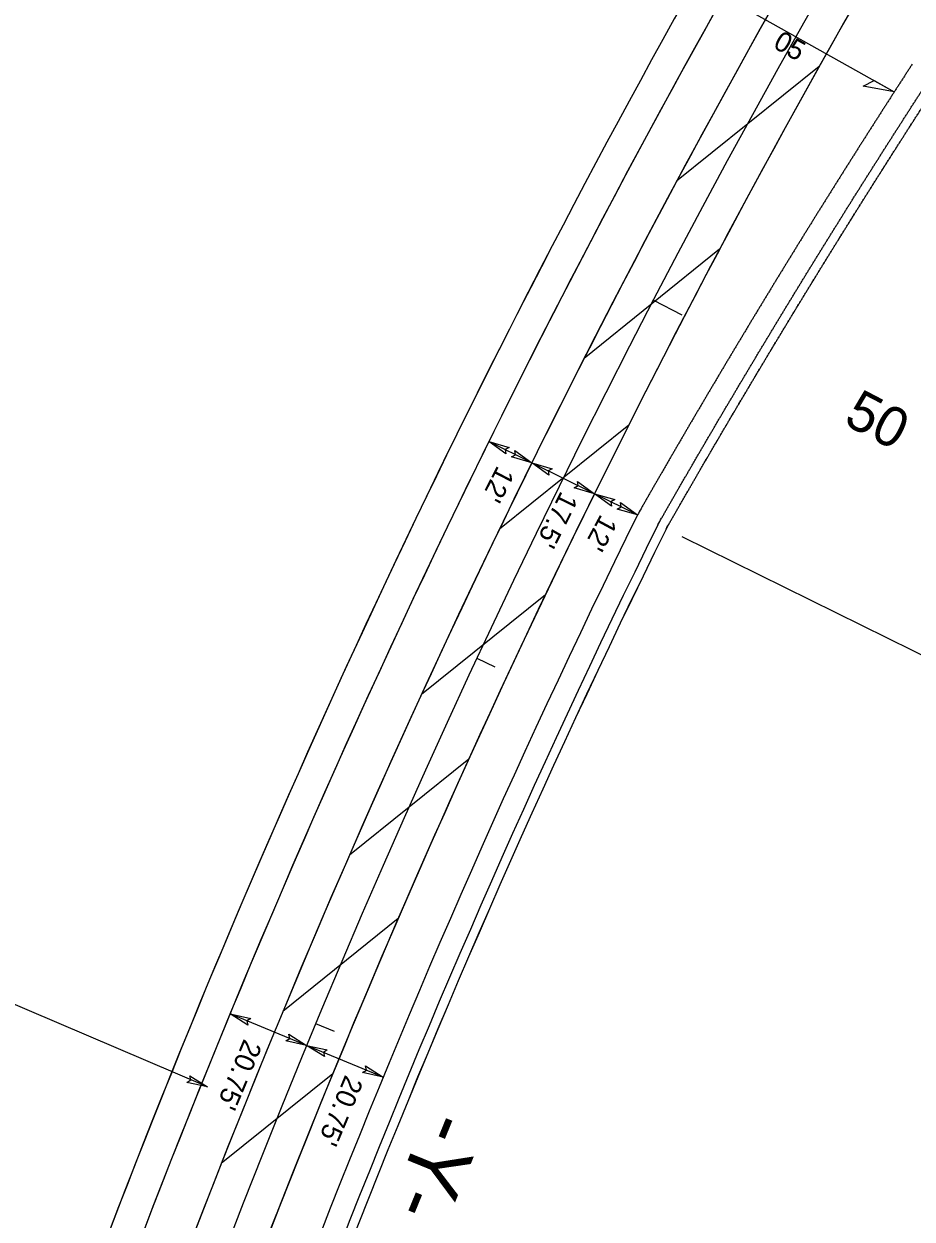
# Model space of a CAD drawing. Extents: x 1778969 to 1790720, y 807089 to 817794.
# Drawn here: x 1781084.1 to 1781306.5, y 812371.1 to 812670.4 of the extents above; entities that cross this region are included whole.
import ezdxf

# ---------------------------------------------------------------- set-up
doc = ezdxf.new("R2010")
doc.units = 0
for name, color, linetype in [('Prop CMT Guardrail Graphics', 7, 'Continuous'), ('Prop Conc Shoulder Berm Gutter', 7, 'Continuous'), ('Prop Dimension', 7, 'Continuous'), ('Prop Dimension Text', 7, 'Continuous'), ('Prop DSN Text', 7, 'Continuous'), ('Prop EOT', 7, 'Continuous'), ('Prop Guardrail', 7, 'Continuous'), ('Prop Hatching', 7, 'Continuous'), ('Prop Horizontal Alignment', 7, 'Continuous'), ('Prop Horizontal Alignment Station Label', 7, 'Continuous'), ('Prop Horizontal Alignment Tick Label', 7, 'Continuous'), ('Prop Horizontal Alignment Tick Large', 7, 'Continuous'), ('Prop Horizontal Alignment Tick Small', 7, 'Continuous'), ('Prop Lane Lines', 7, 'Continuous'), ('Prop Paved Shoulder', 7, 'Continuous'), ('Prop Superelevation  Arrow CELL', 7, 'Continuous'), ('Prop Superelevation Label', 7, 'Continuous'), ('Prop Terminator CELL', 7, 'Continuous'), ('Scratch_Level_3', 7, 'Continuous'), ('Scratch_Level_7', 7, 'Continuous')]:
    doc.layers.add(name, color=color, linetype=linetype)

msp = doc.modelspace()

# ---------------------------------------------------------------- linework, layer by layer
at = {"layer": 'Prop CMT Guardrail Graphics'}
msp.add_arc((1783308.81, 811525.98), 2358.75, 152.51849, 162.35467, dxfattribs=at)
at = {"layer": 'Prop Conc Shoulder Berm Gutter'}
msp.add_arc((1783308.81, 811525.98), 2303.58, 153.74801, 164.19896, dxfattribs=at)
for points in [[(1781276.42, 812601.84), (1781276.89, 812602.6), (1781277.35, 812603.36), (1781277.82, 812604.12), (1781278.28, 812604.88), (1781278.75, 812605.64), (1781279.21, 812606.4), (1781279.68, 812607.16), (1781280.14, 812607.92), (1781280.61, 812608.67), (1781281.08, 812609.43), (1781281.54, 812610.19), (1781282.01, 812610.95), (1781282.48, 812611.71), (1781282.94, 812612.47), (1781283.41, 812613.22), (1781283.88, 812613.98), (1781284.35, 812614.74), (1781284.82, 812615.5), (1781285.29, 812616.25), (1781285.76, 812617.01), (1781286.23, 812617.77), (1781286.7, 812618.52), (1781287.17, 812619.28), (1781287.64, 812620.03), (1781288.11, 812620.79), (1781288.58, 812621.54), (1781289.05, 812622.3), (1781289.52, 812623.06), (1781289.99, 812623.81), (1781290.46, 812624.56), (1781290.94, 812625.32), (1781291.41, 812626.07), (1781291.88, 812626.83), (1781292.36, 812627.58), (1781292.83, 812628.34), (1781293.3, 812629.09), (1781293.78, 812629.84), (1781294.25, 812630.59), (1781294.73, 812631.35), (1781295.2, 812632.1), (1781295.68, 812632.85), (1781296.15, 812633.61), (1781296.63, 812634.36), (1781297.1, 812635.11), (1781297.58, 812635.86), (1781298.06, 812636.61), (1781298.53, 812637.36), (1781299.01, 812638.11), (1781299.49, 812638.87), (1781299.97, 812639.62), (1781300.44, 812640.37), (1781300.92, 812641.12), (1781301.4, 812641.87), (1781301.88, 812642.62), (1781302.36, 812643.37), (1781302.84, 812644.12), (1781303.32, 812644.86), (1781303.8, 812645.61), (1781304.28, 812646.36), (1781304.76, 812647.11), (1781305.24, 812647.86), (1781305.72, 812648.61), (1781306.2, 812649.36), (1781306.68, 812650.1), (1781307.17, 812650.85), (1781307.65, 812651.6), (1781308.13, 812652.35), (1781308.61, 812653.09), (1781309.1, 812653.84), (1781309.58, 812654.59), (1781310.06, 812655.33), (1781310.55, 812656.08), (1781311.03, 812656.82), (1781311.51, 812657.57)], [(1781242.82, 812544.9), (1781243.78, 812546.57), (1781244.22, 812547.35), (1781244.66, 812548.12), (1781245.11, 812548.9), (1781245.55, 812549.67), (1781245.99, 812550.44), (1781246.44, 812551.22), (1781246.88, 812551.99), (1781247.33, 812552.76), (1781247.77, 812553.54), (1781248.22, 812554.31), (1781248.67, 812555.08), (1781249.11, 812555.85), (1781249.56, 812556.63), (1781250.01, 812557.4), (1781250.45, 812558.17), (1781250.9, 812558.94), (1781251.35, 812559.71), (1781251.8, 812560.48), (1781252.25, 812561.25), (1781252.69, 812562.02), (1781253.14, 812562.8), (1781253.59, 812563.57), (1781254.04, 812564.34), (1781254.49, 812565.11), (1781254.94, 812565.88), (1781255.39, 812566.65), (1781255.84, 812567.41), (1781256.3, 812568.18), (1781256.75, 812568.95), (1781257.2, 812569.72), (1781257.65, 812570.49), (1781258.1, 812571.26), (1781258.55, 812572.03), (1781259.01, 812572.8), (1781259.46, 812573.56), (1781259.91, 812574.33), (1781260.37, 812575.1), (1781260.82, 812575.87), (1781261.28, 812576.63), (1781261.73, 812577.4), (1781262.18, 812578.17), (1781262.64, 812578.93), (1781263.1, 812579.7), (1781263.55, 812580.47), (1781264.01, 812581.23), (1781264.46, 812582), (1781264.92, 812582.76), (1781265.38, 812583.53), (1781265.83, 812584.29), (1781266.29, 812585.06), (1781266.75, 812585.82), (1781267.21, 812586.59), (1781267.66, 812587.35), (1781268.12, 812588.12), (1781268.58, 812588.88), (1781269.04, 812589.64), (1781269.5, 812590.41), (1781269.96, 812591.17), (1781270.42, 812591.93), (1781270.88, 812592.7), (1781271.34, 812593.46), (1781271.8, 812594.22), (1781272.26, 812594.99), (1781272.72, 812595.75), (1781273.18, 812596.51), (1781273.65, 812597.27), (1781274.11, 812598.03), (1781274.57, 812598.79), (1781275.03, 812599.56), (1781275.5, 812600.32), (1781275.96, 812601.08), (1781276.42, 812601.84)]]:
    msp.add_spline(points, degree=3, dxfattribs=at)
at = {"layer": 'Prop Dimension'}
for p, q in [((1781211.28, 812560.45), (1781200.52, 812565.76)), ((1781226.98, 812552.71), (1781211.28, 812560.45)), ((1781237.74, 812547.4), (1781226.98, 812552.71)), ((1781314.16, 812509.72), (1781248.9, 812541.9)), ((1781154.9, 812414.56), (1781135.72, 812422.47)), ((1781174.08, 812406.64), (1781154.9, 812414.56))]:
    msp.add_line(p, q, dxfattribs=at)
at = {"layer": 'Prop DSN Text'}
msp.add_line((1781130.09, 812404.16), (1780995.62, 812461.49), dxfattribs=at)
at = {"layer": 'Prop EOT'}
for radius, start, end in [(2350.75, 144.08998, 163.35801), (2309.25, 153.74801, 174.52695)]:
    msp.add_arc((1783308.81, 811525.98), radius, start, end, dxfattribs=at)
for points in [[(1781306.51, 812660.24), (1781306.03, 812659.49), (1781305.54, 812658.75), (1781305.06, 812658), (1781304.57, 812657.25), (1781304.09, 812656.5), (1781303.6, 812655.75), (1781303.12, 812655), (1781302.64, 812654.25), (1781302.15, 812653.5), (1781301.67, 812652.76), (1781301.19, 812652.01), (1781300.7, 812651.26), (1781300.22, 812650.51), (1781299.74, 812649.76), (1781299.26, 812649), (1781298.78, 812648.25), (1781298.3, 812647.5), (1781297.82, 812646.75), (1781297.34, 812646), (1781296.85, 812645.25), (1781296.37, 812644.5), (1781295.9, 812643.75), (1781295.42, 812642.99), (1781294.94, 812642.24), (1781294.46, 812641.49), (1781293.98, 812640.74), (1781293.5, 812639.98), (1781293.02, 812639.23), (1781292.55, 812638.48), (1781292.07, 812637.72), (1781291.59, 812636.97), (1781291.12, 812636.21), (1781290.64, 812635.46), (1781290.16, 812634.71), (1781289.69, 812633.95), (1781289.21, 812633.2), (1781288.74, 812632.44), (1781288.26, 812631.69), (1781287.79, 812630.93), (1781287.31, 812630.18), (1781286.84, 812629.42), (1781286.36, 812628.66), (1781285.89, 812627.91), (1781285.42, 812627.15), (1781284.94, 812626.39), (1781284.47, 812625.64), (1781284, 812624.88), (1781283.52, 812624.12), (1781283.05, 812623.37), (1781282.58, 812622.61), (1781282.11, 812621.85), (1781281.64, 812621.09), (1781281.17, 812620.33), (1781280.7, 812619.58), (1781280.23, 812618.82), (1781279.76, 812618.06), (1781279.29, 812617.3), (1781278.82, 812616.54), (1781278.35, 812615.78), (1781277.88, 812615.02), (1781277.41, 812614.26), (1781276.94, 812613.5), (1781276.48, 812612.74), (1781276.01, 812611.98), (1781275.54, 812611.22), (1781275.07, 812610.46), (1781274.61, 812609.7), (1781274.14, 812608.94), (1781273.67, 812608.18), (1781273.21, 812607.41), (1781272.74, 812606.65), (1781272.28, 812605.89), (1781271.81, 812605.13), (1781271.35, 812604.37)], [(1781271.35, 812604.37), (1781270.88, 812603.6), (1781270.42, 812602.84), (1781269.95, 812602.08), (1781269.49, 812601.31), (1781269.03, 812600.55), (1781268.56, 812599.79), (1781268.1, 812599.02), (1781267.64, 812598.26), (1781267.17, 812597.49), (1781266.71, 812596.73), (1781266.25, 812595.97), (1781265.79, 812595.2), (1781265.33, 812594.44), (1781264.87, 812593.67), (1781264.41, 812592.91), (1781263.95, 812592.14), (1781263.49, 812591.37), (1781263.03, 812590.61), (1781262.57, 812589.84), (1781262.11, 812589.08), (1781261.65, 812588.31), (1781261.19, 812587.54), (1781260.73, 812586.78), (1781260.27, 812586.01), (1781259.82, 812585.24), (1781259.36, 812584.47), (1781258.9, 812583.71), (1781258.45, 812582.94), (1781257.99, 812582.17), (1781257.53, 812581.4), (1781257.08, 812580.63), (1781256.62, 812579.86), (1781256.17, 812579.1), (1781255.71, 812578.33), (1781255.26, 812577.56), (1781254.8, 812576.79), (1781254.35, 812576.02), (1781253.89, 812575.25), (1781253.44, 812574.48), (1781252.99, 812573.71), (1781252.53, 812572.94), (1781252.08, 812572.17), (1781251.63, 812571.4), (1781251.17, 812570.63), (1781250.72, 812569.85), (1781250.27, 812569.08), (1781249.82, 812568.31), (1781249.37, 812567.54), (1781248.92, 812566.77), (1781248.47, 812565.99), (1781248.02, 812565.22), (1781247.57, 812564.45), (1781247.12, 812563.68), (1781246.67, 812562.9), (1781246.22, 812562.13), (1781245.77, 812561.36), (1781245.32, 812560.58), (1781244.87, 812559.81), (1781244.43, 812559.04), (1781243.98, 812558.26), (1781243.53, 812557.49), (1781243.08, 812556.71), (1781242.64, 812555.94), (1781242.19, 812555.16), (1781241.74, 812554.39), (1781241.3, 812553.61), (1781240.85, 812552.84), (1781240.41, 812552.06), (1781239.96, 812551.29), (1781239.52, 812550.51), (1781239.07, 812549.73), (1781238.63, 812548.96), (1781237.74, 812547.4)]]:
    msp.add_spline(points, degree=3, dxfattribs=at)
at = {"layer": 'Prop Guardrail'}
for radius, start, end in [(2358.75, 144.08998, 162.35467), (2301.25, 153.74801, 164.19128)]:
    msp.add_arc((1783308.81, 811525.98), radius, start, end, dxfattribs=at)
for points in [[(1781278.42, 812600.62), (1781278.88, 812601.38), (1781279.34, 812602.14), (1781279.81, 812602.9), (1781280.27, 812603.66), (1781280.74, 812604.42), (1781281.2, 812605.18), (1781281.67, 812605.94), (1781282.13, 812606.69), (1781282.6, 812607.45), (1781283.06, 812608.21), (1781283.53, 812608.97), (1781284, 812609.73), (1781284.46, 812610.48), (1781284.93, 812611.24), (1781285.4, 812612), (1781285.87, 812612.75), (1781286.33, 812613.51), (1781286.8, 812614.27), (1781287.27, 812615.02), (1781287.74, 812615.78), (1781288.21, 812616.53), (1781288.68, 812617.29), (1781289.15, 812618.05), (1781289.62, 812618.8), (1781290.09, 812619.56), (1781290.56, 812620.31), (1781291.03, 812621.06), (1781291.5, 812621.82), (1781291.97, 812622.57), (1781292.44, 812623.33), (1781292.91, 812624.08), (1781293.39, 812624.83), (1781293.86, 812625.59), (1781294.33, 812626.34), (1781294.8, 812627.09), (1781295.28, 812627.85), (1781295.75, 812628.6), (1781296.23, 812629.35), (1781296.7, 812630.1), (1781297.17, 812630.85), (1781297.65, 812631.61), (1781298.12, 812632.36), (1781298.6, 812633.11), (1781299.07, 812633.86), (1781299.55, 812634.61), (1781300.03, 812635.36), (1781300.5, 812636.11), (1781300.98, 812636.86), (1781301.46, 812637.61), (1781301.93, 812638.36), (1781302.41, 812639.11), (1781302.89, 812639.86), (1781303.37, 812640.61), (1781303.85, 812641.36), (1781304.32, 812642.11), (1781304.8, 812642.86), (1781305.28, 812643.61), (1781305.76, 812644.35), (1781306.24, 812645.1), (1781306.72, 812645.85), (1781307.2, 812646.6), (1781307.68, 812647.34), (1781308.16, 812648.09), (1781308.64, 812648.84), (1781309.13, 812649.59), (1781309.61, 812650.33), (1781310.09, 812651.08), (1781310.57, 812651.83), (1781311.05, 812652.57), (1781311.54, 812653.32), (1781312.02, 812654.06), (1781312.5, 812654.81), (1781312.99, 812655.55), (1781313.47, 812656.3)], [(1781244.92, 812543.87), (1781245.8, 812545.41), (1781246.24, 812546.19), (1781246.69, 812546.96), (1781247.13, 812547.73), (1781247.57, 812548.51), (1781248.02, 812549.28), (1781248.46, 812550.05), (1781248.91, 812550.83), (1781249.35, 812551.6), (1781249.8, 812552.37), (1781250.24, 812553.14), (1781250.69, 812553.91), (1781251.13, 812554.69), (1781251.58, 812555.46), (1781252.03, 812556.23), (1781252.47, 812557), (1781252.92, 812557.77), (1781253.37, 812558.54), (1781253.81, 812559.31), (1781254.26, 812560.08), (1781254.71, 812560.85), (1781255.16, 812561.62), (1781255.61, 812562.39), (1781256.06, 812563.16), (1781256.51, 812563.93), (1781256.96, 812564.7), (1781257.41, 812565.47), (1781257.86, 812566.24), (1781258.31, 812567), (1781258.76, 812567.77), (1781259.21, 812568.54), (1781259.66, 812569.31), (1781260.11, 812570.08), (1781260.56, 812570.84), (1781261.02, 812571.61), (1781261.47, 812572.38), (1781261.92, 812573.14), (1781262.38, 812573.91), (1781262.83, 812574.68), (1781263.28, 812575.44), (1781263.74, 812576.21), (1781264.19, 812576.98), (1781264.65, 812577.74), (1781265.1, 812578.51), (1781265.56, 812579.27), (1781266.01, 812580.04), (1781266.47, 812580.8), (1781266.92, 812581.57), (1781267.38, 812582.33), (1781267.84, 812583.1), (1781268.29, 812583.86), (1781268.75, 812584.62), (1781269.21, 812585.39), (1781269.67, 812586.15), (1781270.12, 812586.92), (1781270.58, 812587.68), (1781271.04, 812588.44), (1781271.5, 812589.2), (1781271.96, 812589.97), (1781272.42, 812590.73), (1781272.88, 812591.49), (1781273.34, 812592.25), (1781273.8, 812593.02), (1781274.26, 812593.78), (1781274.72, 812594.54), (1781275.18, 812595.3), (1781275.64, 812596.06), (1781276.1, 812596.82), (1781276.57, 812597.58), (1781277.03, 812598.34), (1781277.49, 812599.1), (1781277.95, 812599.86), (1781278.42, 812600.62)]]:
    msp.add_spline(points, degree=3, dxfattribs=at)
at = {"layer": 'Prop Hatching'}
for p, q in [((1781283.27, 812659.73), (1781247.55, 812630.95)), ((1781258.31, 812613.93), (1781224.38, 812586.6)), ((1781235.55, 812569.91), (1781203.16, 812543.81)), ((1781214.7, 812527.42), (1781183.64, 812502.4)), ((1781195.51, 812486.28), (1781165.63, 812462.2)), ((1781177.81, 812446.34), (1781148.96, 812423.09)), ((1781161.44, 812407.46), (1781133.52, 812384.96))]:
    msp.add_line(p, q, dxfattribs=at)
at = {"layer": 'Prop Horizontal Alignment'}
msp.add_arc((1783308.81, 811525.98), 2330, 144.08998, 185.35942, dxfattribs=at)
at = {"layer": 'Prop Horizontal Alignment Tick Large'}
msp.add_line((1781241.73, 812601.19), (1781248.82, 812597.49), dxfattribs=at)
at = {"layer": 'Prop Horizontal Alignment Tick Small'}
for p, q in [((1781197.5, 812511.51), (1781202.03, 812509.39)), ((1781157.16, 812420.01), (1781161.78, 812418.09))]:
    msp.add_line(p, q, dxfattribs=at)
at = {"layer": 'Prop Lane Lines'}
for radius, start in [(2338.75, 144.36073), (2321.25, 144.3813), (2338.75, 148.12573), (2321.25, 148.12573), (2321.25, 153.74801)]:
    msp.add_arc((1783308.81, 811525.98), radius, start, 163.33829, dxfattribs=at)
at = {"layer": 'Prop Paved Shoulder'}
msp.add_arc((1783308.81, 811525.98), 2358.75, 144.08998, 162.35467, dxfattribs=at)
at = {"layer": 'Prop Superelevation  Arrow CELL'}
msp.add_line((1781259.31, 812677.32), (1781302.03, 812653.32), dxfattribs=at)
msp.add_lwpolyline([(1781302.03, 812653.32), (1781294.27, 812654.81), (1781296.99, 812656.15)], close=True, dxfattribs=at)
at = {"layer": 'Prop Terminator CELL'}
for points in [[(1781204.78, 812562.67), (1781200.52, 812565.76), (1781205.6, 812564.28), (1781204.6, 812563.75)], [(1781207.03, 812563.55), (1781211.28, 812560.45), (1781206.2, 812561.93), (1781207.2, 812562.47)], [(1781215.54, 812557.36), (1781211.28, 812560.45), (1781216.37, 812558.97), (1781215.37, 812558.44)], [(1781222.72, 812555.81), (1781226.98, 812552.71), (1781221.9, 812554.19), (1781222.9, 812554.73)], [(1781231.23, 812549.62), (1781226.98, 812552.71), (1781232.06, 812551.23), (1781231.06, 812550.7)], [(1781233.49, 812550.5), (1781237.74, 812547.4), (1781232.66, 812548.88), (1781233.66, 812549.42)], [(1781140.17, 812419.67), (1781135.72, 812422.47), (1781140.89, 812421.33), (1781139.92, 812420.73)], [(1781150.45, 812417.36), (1781154.9, 812414.56), (1781149.73, 812415.69), (1781150.69, 812416.29)], [(1781159.35, 812411.75), (1781154.9, 812414.56), (1781160.07, 812413.42), (1781159.11, 812412.82)], [(1781169.63, 812409.44), (1781174.08, 812406.64), (1781168.91, 812407.78), (1781169.87, 812408.38)], [(1781125.64, 812406.96), (1781130.09, 812404.16), (1781124.92, 812405.3), (1781125.88, 812405.9)]]:
    msp.add_lwpolyline(points, close=True, dxfattribs=at)
at = {"layer": 'Scratch_Level_3'}
msp.add_arc((1783308.81, 811525.98), 2350.75, 144.08998, 164.89021, dxfattribs=at)
at = {"layer": 'Scratch_Level_7'}
msp.add_arc((1783308.81, 811525.98), 2301.26, 153.74801, 164.19128, dxfattribs=at)
for points in [[(1781278.41, 812600.63), (1781278.87, 812601.39), (1781279.34, 812602.15), (1781279.8, 812602.91), (1781280.26, 812603.67), (1781280.73, 812604.42), (1781281.19, 812605.18), (1781281.66, 812605.94), (1781282.12, 812606.7), (1781282.59, 812607.46), (1781283.05, 812608.22), (1781283.52, 812608.97), (1781283.99, 812609.73), (1781284.45, 812610.49), (1781284.92, 812611.25), (1781285.39, 812612), (1781285.86, 812612.76), (1781286.32, 812613.52), (1781286.79, 812614.27), (1781287.26, 812615.03), (1781287.73, 812615.78), (1781288.2, 812616.54), (1781288.67, 812617.3), (1781289.14, 812618.05), (1781289.61, 812618.81), (1781290.08, 812619.56), (1781290.55, 812620.32), (1781291.02, 812621.07), (1781291.49, 812621.82), (1781291.96, 812622.58), (1781292.43, 812623.33), (1781292.91, 812624.09), (1781293.38, 812624.84), (1781293.85, 812625.59), (1781294.32, 812626.35), (1781294.8, 812627.1), (1781295.27, 812627.85), (1781295.74, 812628.6), (1781296.22, 812629.36), (1781296.69, 812630.11), (1781297.17, 812630.86), (1781297.64, 812631.61), (1781298.12, 812632.36), (1781298.59, 812633.11), (1781299.07, 812633.87), (1781299.54, 812634.62), (1781300.02, 812635.37), (1781300.49, 812636.12), (1781300.97, 812636.87), (1781301.45, 812637.62), (1781301.93, 812638.37), (1781302.4, 812639.12), (1781302.88, 812639.87), (1781303.36, 812640.62), (1781303.84, 812641.37), (1781304.32, 812642.11), (1781304.8, 812642.86), (1781305.27, 812643.61), (1781305.75, 812644.36), (1781306.23, 812645.11), (1781306.71, 812645.86), (1781307.19, 812646.6), (1781307.67, 812647.35), (1781308.16, 812648.1), (1781308.64, 812648.84), (1781309.12, 812649.59), (1781309.6, 812650.34), (1781310.08, 812651.08), (1781310.56, 812651.83), (1781311.05, 812652.58), (1781311.53, 812653.32), (1781312.01, 812654.07), (1781312.5, 812654.81), (1781312.98, 812655.56), (1781313.46, 812656.3)], [(1781244.91, 812543.87), (1781245.79, 812545.42), (1781246.23, 812546.19), (1781246.68, 812546.97), (1781247.12, 812547.74), (1781247.56, 812548.51), (1781248.01, 812549.29), (1781248.45, 812550.06), (1781248.9, 812550.83), (1781249.34, 812551.6), (1781249.79, 812552.37), (1781250.23, 812553.15), (1781250.68, 812553.92), (1781251.12, 812554.69), (1781251.57, 812555.46), (1781252.02, 812556.23), (1781252.46, 812557), (1781252.91, 812557.77), (1781253.36, 812558.54), (1781253.81, 812559.32), (1781254.25, 812560.09), (1781254.7, 812560.86), (1781255.15, 812561.63), (1781255.6, 812562.39), (1781256.05, 812563.16), (1781256.5, 812563.93), (1781256.95, 812564.7), (1781257.4, 812565.47), (1781257.85, 812566.24), (1781258.3, 812567.01), (1781258.75, 812567.78), (1781259.2, 812568.54), (1781259.65, 812569.31), (1781260.1, 812570.08), (1781260.56, 812570.85), (1781261.01, 812571.62), (1781261.46, 812572.38), (1781261.91, 812573.15), (1781262.37, 812573.92), (1781262.82, 812574.68), (1781263.27, 812575.45), (1781263.73, 812576.22), (1781264.18, 812576.98), (1781264.64, 812577.75), (1781265.09, 812578.51), (1781265.55, 812579.28), (1781266, 812580.04), (1781266.46, 812580.81), (1781266.91, 812581.57), (1781267.37, 812582.34), (1781267.83, 812583.1), (1781268.28, 812583.87), (1781268.74, 812584.63), (1781269.2, 812585.39), (1781269.66, 812586.16), (1781270.11, 812586.92), (1781270.57, 812587.68), (1781271.03, 812588.45), (1781271.49, 812589.21), (1781271.95, 812589.97), (1781272.41, 812590.73), (1781272.87, 812591.5), (1781273.33, 812592.26), (1781273.79, 812593.02), (1781274.25, 812593.78), (1781274.71, 812594.54), (1781275.17, 812595.31), (1781275.63, 812596.07), (1781276.09, 812596.83), (1781276.56, 812597.59), (1781277.02, 812598.35), (1781277.48, 812599.11), (1781277.94, 812599.87), (1781278.41, 812600.63)]]:
    msp.add_spline(points, degree=3, dxfattribs=at)

# ---------------------------------------------------------------- texts
at = {"layer": 'Prop Dimension Text'}
for s, rotation, p in [("12'", 242.9248, (1781202.7, 812559.97)), ("17.5'", 243.5702, (1781218.6, 812553.57)), ("12'", 241.6319, (1781228.56, 812547.79)), ("20.75'", 247.2201, (1781139.24, 812416.39)), ("20.75'", 247.2201, (1781164.6, 812407.38))]:
    msp.add_text(s, height=5, rotation=rotation, dxfattribs=at).set_placement(p)
at = {"layer": 'Prop Horizontal Alignment Station Label'}
msp.add_text('-Y-', height=15, rotation=247.8136, dxfattribs=at).set_placement((1781185.57, 812399.02))
at = {"layer": 'Prop Horizontal Alignment Tick Label'}
msp.add_text('50', height=10, rotation=332.5185, dxfattribs=at).set_placement((1781289.01, 812570.31))
at = {"layer": 'Prop Superelevation Label'}
msp.add_text('05', height=5, rotation=330.6742, dxfattribs=at).set_placement((1781271.44, 812664.53))

doc.saveas('drawing.dxf')
